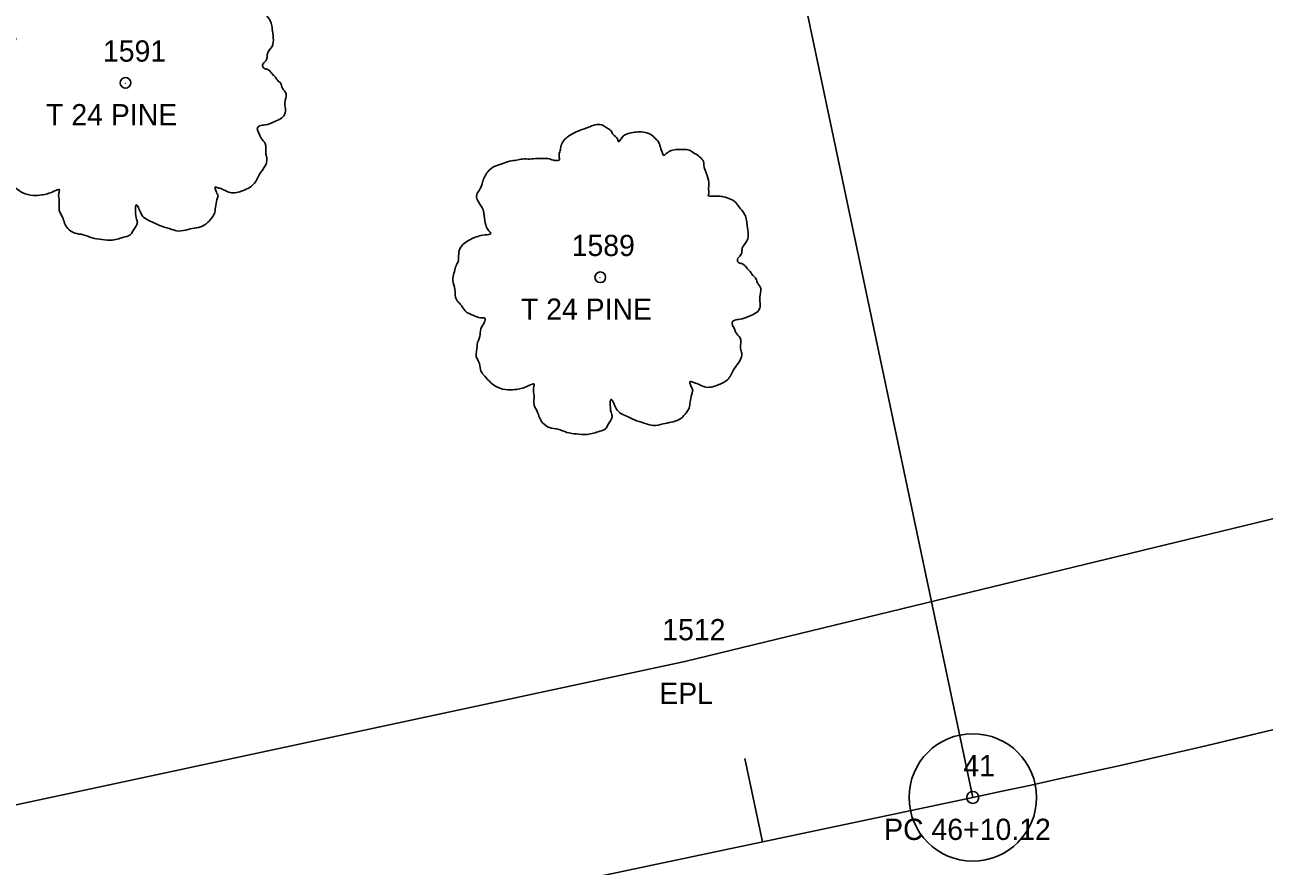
# Model space of a CAD drawing. Extents: x 1964982 to 1970452, y 1116335 to 1119906.
# Drawn here: x 1966640.3 to 1966698.6, y 1117418.7 to 1117458.3 of the extents above; entities that cross this region are included whole.
import ezdxf

# ---------------------------------------------------------------- set-up
doc = ezdxf.new("R2010")
doc.units = 0
for name, color, linetype in [('RD_EX_DV_Prop', 7, 'Continuous'), ('RD_EX_Road', 7, 'Continuous'), ('RD_EX_Road_txCode', 7, 'Continuous'), ('RD_EX_RW', 7, 'Continuous'), ('RD_EX_VEG', 7, 'Continuous'), ('RD_EX_VEG_txCode', 7, 'Continuous'), ('RD_HC_CL', 7, 'Continuous'), ('RD_HC_Data', 7, 'Continuous'), ('RD_HC_Data_Tic', 7, 'Continuous'), ('RD_HC_txCode', 7, 'Continuous'), ('RD_SMD_Locator', 7, 'Continuous')]:
    doc.layers.add(name, color=color, linetype=linetype)

msp = doc.modelspace()

# ---------------------------------------------------------------- linework, layer by layer
at = {"layer": 'RD_EX_DV_Prop'}
msp.add_line((1966425.261, 1117367.215), (1966684.872, 1117421.945), dxfattribs=at)
msp.add_arc((1966579.594, 1117921.318), 510.35, 281.90473, 291.99584, dxfattribs=at)
at = {"layer": 'RD_EX_Road'}
msp.add_lwpolyline([(1966484.547, 1117389.131), (1966531.199, 1117398.733), (1966578.388, 1117408.593), (1966604.527, 1117414.058), (1966624.537, 1117418.323), (1966671.319, 1117428.348), (1966716.506, 1117439.32), (1966736.604, 1117445.59), (1966754.133, 1117451.442), (1966759.658, 1117453.517), (1966769.512, 1117457.475)], dxfattribs=at)
at = {"layer": 'RD_EX_RW'}
msp.add_lwpolyline([(1966484.547, 1117389.131), (1966531.199, 1117398.733), (1966578.388, 1117408.593), (1966604.527, 1117414.058), (1966624.537, 1117418.323), (1966671.319, 1117428.348), (1966716.506, 1117439.32), (1966736.604, 1117445.59), (1966754.133, 1117451.442), (1966759.658, 1117453.517), (1966769.512, 1117457.475)], dxfattribs=at)
at = {"layer": 'RD_EX_VEG'}
for centre, radius in [((1966644.994, 1117455.597), 0.25), ((1966644.994, 1117455.597), 0.25), ((1966644.981, 1117455.578), 0.0001), ((1966644.981, 1117455.578), 0.0001), ((1966667.339, 1117446.441), 0.25), ((1966667.339, 1117446.441), 0.25), ((1966667.326, 1117446.422), 0.0001), ((1966667.326, 1117446.422), 0.0001)]:
    msp.add_circle(centre, radius, dxfattribs=at)
for points in [[(1966645.126, 1117462.764), (1966644.826, 1117462.789), (1966644.501, 1117462.689), (1966644.251, 1117462.589), (1966644.026, 1117462.514), (1966643.801, 1117462.414), (1966643.501, 1117462.24), (1966643.276, 1117462.04), (1966643.151, 1117461.79), (1966643.101, 1117461.565), (1966643.052, 1117461.29), (1966643.052, 1117461.115), (1966642.927, 1117461.09), (1966642.777, 1117461.115), (1966642.527, 1117461.19), (1966642.277, 1117461.19), (1966642.027, 1117461.19), (1966641.677, 1117461.165), (1966641.327, 1117461.165), (1966641.052, 1117461.115), (1966640.728, 1117461.065), (1966640.353, 1117460.94), (1966640.003, 1117460.815), (1966639.703, 1117460.565), (1966639.453, 1117460.09), (1966639.328, 1117459.741), (1966639.178, 1117459.491), (1966639.328, 1117459.041), (1966639.503, 1117458.691), (1966639.528, 1117458.491), (1966639.603, 1117458.066), (1966639.703, 1117457.841), (1966639.828, 1117457.641), (1966639.753, 1117457.617), (1966639.378, 1117457.567), (1966639.078, 1117457.467), (1966638.653, 1117457.242), (1966638.429, 1117457.017), (1966638.329, 1117456.692), (1966638.304, 1117456.342), (1966638.204, 1117456.142), (1966638.129, 1117455.867), (1966638.104, 1117455.792), (1966638.054, 1117455.467), (1966638.154, 1117455.018), (1966638.179, 1117454.668), (1966638.304, 1117454.443), (1966638.454, 1117454.268), (1966638.628, 1117454.018), (1966639.028, 1117453.793), (1966639.353, 1117453.693), (1966639.553, 1117453.668), (1966639.378, 1117453.168), (1966639.328, 1117452.819), (1966639.203, 1117452.419), (1966639.203, 1117452.344), (1966639.153, 1117451.869), (1966639.303, 1117451.544), (1966639.378, 1117451.169), (1966639.553, 1117450.944), (1966639.828, 1117450.645), (1966640.153, 1117450.42), (1966640.653, 1117450.295), (1966641.052, 1117450.32), (1966641.627, 1117450.495), (1966641.877, 1117450.57), (1966641.852, 1117450.395), (1966641.877, 1117450.02), (1966641.877, 1117449.595), (1966642.027, 1117449.27), (1966642.127, 1117448.995), (1966642.277, 1117448.745), (1966642.602, 1117448.521), (1966643.002, 1117448.446), (1966643.426, 1117448.296), (1966643.876, 1117448.221), (1966644.376, 1117448.196), (1966644.976, 1117448.346), (1966645.251, 1117448.471), (1966645.351, 1117448.645), (1966645.55, 1117449.02), (1966645.5, 1117449.245), (1966645.525, 1117449.845), (1966645.625, 1117449.67), (1966645.8, 1117449.32), (1966646.3, 1117449.02), (1966646.7, 1117448.845), (1966647.175, 1117448.695), (1966647.475, 1117448.62), (1966647.949, 1117448.695), (1966648.324, 1117448.77), (1966648.699, 1117448.895), (1966648.999, 1117449.17), (1966649.174, 1117449.445), (1966649.224, 1117449.72), (1966649.299, 1117450.095), (1966649.349, 1117450.27)], [(1966645.126, 1117462.764), (1966644.826, 1117462.789), (1966644.501, 1117462.689), (1966644.251, 1117462.589), (1966644.026, 1117462.514), (1966643.801, 1117462.414), (1966643.501, 1117462.24), (1966643.276, 1117462.04), (1966643.151, 1117461.79), (1966643.101, 1117461.565), (1966643.052, 1117461.29), (1966643.052, 1117461.115), (1966642.927, 1117461.09), (1966642.777, 1117461.115), (1966642.527, 1117461.19), (1966642.277, 1117461.19), (1966642.027, 1117461.19), (1966641.677, 1117461.165), (1966641.327, 1117461.165), (1966641.052, 1117461.115), (1966640.728, 1117461.065), (1966640.353, 1117460.94), (1966640.003, 1117460.815), (1966639.703, 1117460.565), (1966639.453, 1117460.09), (1966639.328, 1117459.741), (1966639.178, 1117459.491), (1966639.328, 1117459.041), (1966639.503, 1117458.691), (1966639.528, 1117458.491), (1966639.603, 1117458.066), (1966639.703, 1117457.841), (1966639.828, 1117457.641), (1966639.753, 1117457.617), (1966639.378, 1117457.567), (1966639.078, 1117457.467), (1966638.653, 1117457.242), (1966638.429, 1117457.017), (1966638.329, 1117456.692), (1966638.304, 1117456.342), (1966638.204, 1117456.142), (1966638.129, 1117455.867), (1966638.104, 1117455.792), (1966638.054, 1117455.467), (1966638.154, 1117455.018), (1966638.179, 1117454.668), (1966638.304, 1117454.443), (1966638.454, 1117454.268), (1966638.628, 1117454.018), (1966639.028, 1117453.793), (1966639.353, 1117453.693), (1966639.553, 1117453.668), (1966639.378, 1117453.168), (1966639.328, 1117452.819), (1966639.203, 1117452.419), (1966639.203, 1117452.344), (1966639.153, 1117451.869), (1966639.303, 1117451.544), (1966639.378, 1117451.169), (1966639.553, 1117450.944), (1966639.828, 1117450.645), (1966640.153, 1117450.42), (1966640.653, 1117450.295), (1966641.052, 1117450.32), (1966641.627, 1117450.495), (1966641.877, 1117450.57), (1966641.852, 1117450.395), (1966641.877, 1117450.02), (1966641.877, 1117449.595), (1966642.027, 1117449.27), (1966642.127, 1117448.995), (1966642.277, 1117448.745), (1966642.602, 1117448.521), (1966643.002, 1117448.446), (1966643.426, 1117448.296), (1966643.876, 1117448.221), (1966644.376, 1117448.196), (1966644.976, 1117448.346), (1966645.251, 1117448.471), (1966645.351, 1117448.645), (1966645.55, 1117449.02), (1966645.5, 1117449.245), (1966645.525, 1117449.845), (1966645.625, 1117449.67), (1966645.8, 1117449.32), (1966646.3, 1117449.02), (1966646.7, 1117448.845), (1966647.175, 1117448.695), (1966647.475, 1117448.62), (1966647.949, 1117448.695), (1966648.324, 1117448.77), (1966648.699, 1117448.895), (1966648.999, 1117449.17), (1966649.174, 1117449.445), (1966649.224, 1117449.72), (1966649.299, 1117450.095), (1966649.349, 1117450.27)], [(1966649.349, 1117450.27), (1966649.274, 1117450.445), (1966649.224, 1117450.695), (1966649.299, 1117450.67), (1966649.474, 1117450.62), (1966649.749, 1117450.495), (1966649.974, 1117450.42), (1966650.298, 1117450.445), (1966650.573, 1117450.545), (1966651.023, 1117450.82), (1966651.298, 1117451.294), (1966651.573, 1117451.694), (1966651.648, 1117452.019), (1966651.598, 1117452.244), (1966651.573, 1117452.744), (1966651.373, 1117452.994), (1966651.323, 1117453.118), (1966651.223, 1117453.518), (1966651.298, 1117453.568), (1966651.573, 1117453.618), (1966651.948, 1117453.743), (1966652.223, 1117453.868), (1966652.447, 1117454.043), (1966652.522, 1117454.268), (1966652.497, 1117454.668), (1966652.547, 1117455.068), (1966652.472, 1117455.218), (1966652.372, 1117455.367), (1966652.297, 1117455.567), (1966652.148, 1117455.717), (1966652.048, 1117455.867), (1966651.948, 1117455.967), (1966651.823, 1117456.117), (1966651.648, 1117456.242), (1966651.498, 1117456.292), (1966651.448, 1117456.442), (1966651.598, 1117456.642), (1966651.648, 1117456.742), (1966651.673, 1117456.967), (1966651.898, 1117457.317), (1966651.948, 1117457.716), (1966651.898, 1117458.141), (1966651.848, 1117458.416), (1966651.698, 1117458.691), (1966651.498, 1117458.941), (1966651.373, 1117459.116), (1966651.198, 1117459.241), (1966650.873, 1117459.366), (1966650.623, 1117459.416), (1966650.273, 1117459.416), (1966650.073, 1117459.466), (1966650.098, 1117459.516), (1966650.098, 1117459.666), (1966650.098, 1117459.941), (1966650.023, 1117460.39), (1966649.874, 1117460.89), (1966649.874, 1117460.915), (1966649.774, 1117461.165), (1966649.549, 1117461.365), (1966649.374, 1117461.465), (1966649.174, 1117461.59), (1966648.924, 1117461.615), (1966648.624, 1117461.615), (1966648.349, 1117461.565), (1966648.149, 1117461.465), (1966647.974, 1117461.34), (1966647.899, 1117461.49), (1966647.799, 1117461.79), (1966647.749, 1117461.94), (1966647.6, 1117462.115), (1966647.375, 1117462.314), (1966646.925, 1117462.439), (1966646.3, 1117462.364), (1966646, 1117462.165), (1966645.85, 1117461.99), (1966645.8, 1117462.115), (1966645.6, 1117462.314), (1966645.5, 1117462.489), (1966645.326, 1117462.614), (1966645.176, 1117462.714), (1966645.076, 1117462.764)], [(1966649.349, 1117450.27), (1966649.274, 1117450.445), (1966649.224, 1117450.695), (1966649.299, 1117450.67), (1966649.474, 1117450.62), (1966649.749, 1117450.495), (1966649.974, 1117450.42), (1966650.298, 1117450.445), (1966650.573, 1117450.545), (1966651.023, 1117450.82), (1966651.298, 1117451.294), (1966651.573, 1117451.694), (1966651.648, 1117452.019), (1966651.598, 1117452.244), (1966651.573, 1117452.744), (1966651.373, 1117452.994), (1966651.323, 1117453.118), (1966651.223, 1117453.518), (1966651.298, 1117453.568), (1966651.573, 1117453.618), (1966651.948, 1117453.743), (1966652.223, 1117453.868), (1966652.447, 1117454.043), (1966652.522, 1117454.268), (1966652.497, 1117454.668), (1966652.547, 1117455.068), (1966652.472, 1117455.218), (1966652.372, 1117455.367), (1966652.297, 1117455.567), (1966652.148, 1117455.717), (1966652.048, 1117455.867), (1966651.948, 1117455.967), (1966651.823, 1117456.117), (1966651.648, 1117456.242), (1966651.498, 1117456.292), (1966651.448, 1117456.442), (1966651.598, 1117456.642), (1966651.648, 1117456.742), (1966651.673, 1117456.967), (1966651.898, 1117457.317), (1966651.948, 1117457.716), (1966651.898, 1117458.141), (1966651.848, 1117458.416), (1966651.698, 1117458.691), (1966651.498, 1117458.941), (1966651.373, 1117459.116), (1966651.198, 1117459.241), (1966650.873, 1117459.366), (1966650.623, 1117459.416), (1966650.273, 1117459.416), (1966650.073, 1117459.466), (1966650.098, 1117459.516), (1966650.098, 1117459.666), (1966650.098, 1117459.941), (1966650.023, 1117460.39), (1966649.874, 1117460.89), (1966649.874, 1117460.915), (1966649.774, 1117461.165), (1966649.549, 1117461.365), (1966649.374, 1117461.465), (1966649.174, 1117461.59), (1966648.924, 1117461.615), (1966648.624, 1117461.615), (1966648.349, 1117461.565), (1966648.149, 1117461.465), (1966647.974, 1117461.34), (1966647.899, 1117461.49), (1966647.799, 1117461.79), (1966647.749, 1117461.94), (1966647.6, 1117462.115), (1966647.375, 1117462.314), (1966646.925, 1117462.439), (1966646.3, 1117462.364), (1966646, 1117462.165), (1966645.85, 1117461.99), (1966645.8, 1117462.115), (1966645.6, 1117462.314), (1966645.5, 1117462.489), (1966645.326, 1117462.614), (1966645.176, 1117462.714), (1966645.076, 1117462.764)], [(1966667.471, 1117453.608), (1966667.171, 1117453.633), (1966666.846, 1117453.533), (1966666.596, 1117453.433), (1966666.371, 1117453.358), (1966666.146, 1117453.258), (1966665.846, 1117453.083), (1966665.622, 1117452.883), (1966665.497, 1117452.634), (1966665.447, 1117452.409), (1966665.397, 1117452.134), (1966665.397, 1117451.959), (1966665.272, 1117451.934), (1966665.122, 1117451.959), (1966664.872, 1117452.034), (1966664.622, 1117452.034), (1966664.372, 1117452.034), (1966664.022, 1117452.009), (1966663.672, 1117452.009), (1966663.398, 1117451.959), (1966663.073, 1117451.909), (1966662.698, 1117451.784), (1966662.348, 1117451.659), (1966662.048, 1117451.409), (1966661.798, 1117450.934), (1966661.673, 1117450.584), (1966661.523, 1117450.335), (1966661.673, 1117449.885), (1966661.848, 1117449.535), (1966661.873, 1117449.335), (1966661.948, 1117448.91), (1966662.048, 1117448.685), (1966662.173, 1117448.485), (1966662.098, 1117448.46), (1966661.723, 1117448.41), (1966661.423, 1117448.31), (1966660.999, 1117448.086), (1966660.774, 1117447.861), (1966660.674, 1117447.536), (1966660.649, 1117447.186), (1966660.549, 1117446.986), (1966660.474, 1117446.711), (1966660.449, 1117446.636), (1966660.399, 1117446.311), (1966660.499, 1117445.861), (1966660.524, 1117445.512), (1966660.649, 1117445.287), (1966660.799, 1117445.112), (1966660.974, 1117444.862), (1966661.373, 1117444.637), (1966661.698, 1117444.537), (1966661.898, 1117444.512), (1966661.723, 1117444.012), (1966661.673, 1117443.662), (1966661.548, 1117443.263), (1966661.548, 1117443.188), (1966661.498, 1117442.713), (1966661.648, 1117442.388), (1966661.723, 1117442.013), (1966661.898, 1117441.788), (1966662.173, 1117441.488), (1966662.498, 1117441.264), (1966662.998, 1117441.139), (1966663.398, 1117441.164), (1966663.972, 1117441.338), (1966664.222, 1117441.413), (1966664.197, 1117441.239), (1966664.222, 1117440.864), (1966664.222, 1117440.439), (1966664.372, 1117440.114), (1966664.472, 1117439.839), (1966664.622, 1117439.589), (1966664.947, 1117439.364), (1966665.347, 1117439.289), (1966665.771, 1117439.139), (1966666.221, 1117439.064), (1966666.721, 1117439.039), (1966667.321, 1117439.189), (1966667.596, 1117439.314), (1966667.696, 1117439.489), (1966667.896, 1117439.864), (1966667.846, 1117440.089), (1966667.871, 1117440.689), (1966667.97, 1117440.514), (1966668.145, 1117440.164), (1966668.645, 1117439.864), (1966669.045, 1117439.689), (1966669.52, 1117439.539), (1966669.82, 1117439.464), (1966670.294, 1117439.539), (1966670.669, 1117439.614), (1966671.044, 1117439.739), (1966671.344, 1117440.014), (1966671.519, 1117440.289), (1966671.569, 1117440.564), (1966671.644, 1117440.939), (1966671.694, 1117441.114)], [(1966667.471, 1117453.608), (1966667.171, 1117453.633), (1966666.846, 1117453.533), (1966666.596, 1117453.433), (1966666.371, 1117453.358), (1966666.146, 1117453.258), (1966665.846, 1117453.083), (1966665.622, 1117452.883), (1966665.497, 1117452.634), (1966665.447, 1117452.409), (1966665.397, 1117452.134), (1966665.397, 1117451.959), (1966665.272, 1117451.934), (1966665.122, 1117451.959), (1966664.872, 1117452.034), (1966664.622, 1117452.034), (1966664.372, 1117452.034), (1966664.022, 1117452.009), (1966663.672, 1117452.009), (1966663.398, 1117451.959), (1966663.073, 1117451.909), (1966662.698, 1117451.784), (1966662.348, 1117451.659), (1966662.048, 1117451.409), (1966661.798, 1117450.934), (1966661.673, 1117450.584), (1966661.523, 1117450.335), (1966661.673, 1117449.885), (1966661.848, 1117449.535), (1966661.873, 1117449.335), (1966661.948, 1117448.91), (1966662.048, 1117448.685), (1966662.173, 1117448.485), (1966662.098, 1117448.46), (1966661.723, 1117448.41), (1966661.423, 1117448.31), (1966660.999, 1117448.086), (1966660.774, 1117447.861), (1966660.674, 1117447.536), (1966660.649, 1117447.186), (1966660.549, 1117446.986), (1966660.474, 1117446.711), (1966660.449, 1117446.636), (1966660.399, 1117446.311), (1966660.499, 1117445.861), (1966660.524, 1117445.512), (1966660.649, 1117445.287), (1966660.799, 1117445.112), (1966660.974, 1117444.862), (1966661.373, 1117444.637), (1966661.698, 1117444.537), (1966661.898, 1117444.512), (1966661.723, 1117444.012), (1966661.673, 1117443.662), (1966661.548, 1117443.263), (1966661.548, 1117443.188), (1966661.498, 1117442.713), (1966661.648, 1117442.388), (1966661.723, 1117442.013), (1966661.898, 1117441.788), (1966662.173, 1117441.488), (1966662.498, 1117441.264), (1966662.998, 1117441.139), (1966663.398, 1117441.164), (1966663.972, 1117441.338), (1966664.222, 1117441.413), (1966664.197, 1117441.239), (1966664.222, 1117440.864), (1966664.222, 1117440.439), (1966664.372, 1117440.114), (1966664.472, 1117439.839), (1966664.622, 1117439.589), (1966664.947, 1117439.364), (1966665.347, 1117439.289), (1966665.771, 1117439.139), (1966666.221, 1117439.064), (1966666.721, 1117439.039), (1966667.321, 1117439.189), (1966667.596, 1117439.314), (1966667.696, 1117439.489), (1966667.896, 1117439.864), (1966667.846, 1117440.089), (1966667.871, 1117440.689), (1966667.97, 1117440.514), (1966668.145, 1117440.164), (1966668.645, 1117439.864), (1966669.045, 1117439.689), (1966669.52, 1117439.539), (1966669.82, 1117439.464), (1966670.294, 1117439.539), (1966670.669, 1117439.614), (1966671.044, 1117439.739), (1966671.344, 1117440.014), (1966671.519, 1117440.289), (1966671.569, 1117440.564), (1966671.644, 1117440.939), (1966671.694, 1117441.114)], [(1966671.694, 1117441.114), (1966671.619, 1117441.289), (1966671.569, 1117441.538), (1966671.644, 1117441.513), (1966671.819, 1117441.463), (1966672.094, 1117441.338), (1966672.319, 1117441.264), (1966672.643, 1117441.289), (1966672.918, 1117441.388), (1966673.368, 1117441.663), (1966673.643, 1117442.138), (1966673.918, 1117442.538), (1966673.993, 1117442.863), (1966673.943, 1117443.088), (1966673.918, 1117443.587), (1966673.718, 1117443.837), (1966673.668, 1117443.962), (1966673.568, 1117444.362), (1966673.643, 1117444.412), (1966673.918, 1117444.462), (1966674.293, 1117444.587), (1966674.568, 1117444.712), (1966674.793, 1117444.887), (1966674.867, 1117445.112), (1966674.843, 1117445.512), (1966674.892, 1117445.911), (1966674.818, 1117446.061), (1966674.718, 1117446.211), (1966674.643, 1117446.411), (1966674.493, 1117446.561), (1966674.393, 1117446.711), (1966674.293, 1117446.811), (1966674.168, 1117446.961), (1966673.993, 1117447.086), (1966673.843, 1117447.136), (1966673.793, 1117447.286), (1966673.943, 1117447.486), (1966673.993, 1117447.586), (1966674.018, 1117447.811), (1966674.243, 1117448.16), (1966674.293, 1117448.56), (1966674.243, 1117448.985), (1966674.193, 1117449.26), (1966674.043, 1117449.535), (1966673.843, 1117449.785), (1966673.718, 1117449.96), (1966673.543, 1117450.085), (1966673.218, 1117450.21), (1966672.968, 1117450.26), (1966672.618, 1117450.26), (1966672.419, 1117450.31), (1966672.444, 1117450.36), (1966672.444, 1117450.509), (1966672.444, 1117450.784), (1966672.369, 1117451.234), (1966672.219, 1117451.734), (1966672.219, 1117451.759), (1966672.119, 1117452.009), (1966671.894, 1117452.209), (1966671.719, 1117452.309), (1966671.519, 1117452.434), (1966671.269, 1117452.459), (1966670.969, 1117452.459), (1966670.694, 1117452.409), (1966670.494, 1117452.309), (1966670.319, 1117452.184), (1966670.244, 1117452.334), (1966670.145, 1117452.634), (1966670.095, 1117452.783), (1966669.945, 1117452.958), (1966669.72, 1117453.158), (1966669.27, 1117453.283), (1966668.645, 1117453.208), (1966668.345, 1117453.008), (1966668.195, 1117452.833), (1966668.145, 1117452.958), (1966667.945, 1117453.158), (1966667.846, 1117453.333), (1966667.671, 1117453.458), (1966667.521, 1117453.558), (1966667.421, 1117453.608)], [(1966671.694, 1117441.114), (1966671.619, 1117441.289), (1966671.569, 1117441.538), (1966671.644, 1117441.513), (1966671.819, 1117441.463), (1966672.094, 1117441.338), (1966672.319, 1117441.264), (1966672.643, 1117441.289), (1966672.918, 1117441.388), (1966673.368, 1117441.663), (1966673.643, 1117442.138), (1966673.918, 1117442.538), (1966673.993, 1117442.863), (1966673.943, 1117443.088), (1966673.918, 1117443.587), (1966673.718, 1117443.837), (1966673.668, 1117443.962), (1966673.568, 1117444.362), (1966673.643, 1117444.412), (1966673.918, 1117444.462), (1966674.293, 1117444.587), (1966674.568, 1117444.712), (1966674.793, 1117444.887), (1966674.867, 1117445.112), (1966674.843, 1117445.512), (1966674.892, 1117445.911), (1966674.818, 1117446.061), (1966674.718, 1117446.211), (1966674.643, 1117446.411), (1966674.493, 1117446.561), (1966674.393, 1117446.711), (1966674.293, 1117446.811), (1966674.168, 1117446.961), (1966673.993, 1117447.086), (1966673.843, 1117447.136), (1966673.793, 1117447.286), (1966673.943, 1117447.486), (1966673.993, 1117447.586), (1966674.018, 1117447.811), (1966674.243, 1117448.16), (1966674.293, 1117448.56), (1966674.243, 1117448.985), (1966674.193, 1117449.26), (1966674.043, 1117449.535), (1966673.843, 1117449.785), (1966673.718, 1117449.96), (1966673.543, 1117450.085), (1966673.218, 1117450.21), (1966672.968, 1117450.26), (1966672.618, 1117450.26), (1966672.419, 1117450.31), (1966672.444, 1117450.36), (1966672.444, 1117450.509), (1966672.444, 1117450.784), (1966672.369, 1117451.234), (1966672.219, 1117451.734), (1966672.219, 1117451.759), (1966672.119, 1117452.009), (1966671.894, 1117452.209), (1966671.719, 1117452.309), (1966671.519, 1117452.434), (1966671.269, 1117452.459), (1966670.969, 1117452.459), (1966670.694, 1117452.409), (1966670.494, 1117452.309), (1966670.319, 1117452.184), (1966670.244, 1117452.334), (1966670.145, 1117452.634), (1966670.095, 1117452.783), (1966669.945, 1117452.958), (1966669.72, 1117453.158), (1966669.27, 1117453.283), (1966668.645, 1117453.208), (1966668.345, 1117453.008), (1966668.195, 1117452.833), (1966668.145, 1117452.958), (1966667.945, 1117453.158), (1966667.846, 1117453.333), (1966667.671, 1117453.458), (1966667.521, 1117453.558), (1966667.421, 1117453.608)]]:
    msp.add_spline(points, degree=3, dxfattribs=at)
at = {"layer": 'RD_HC_CL'}
msp.add_line((1966425.261, 1117367.215), (1966684.871, 1117421.945), dxfattribs=at)
msp.add_arc((1966579.594, 1117921.318), 510.35, 281.90472, 291.99584, dxfattribs=at)
at = {"layer": 'RD_HC_Data'}
msp.add_line((1966684.871, 1117421.945), (1966664.447, 1117518.825), dxfattribs=at)
for radius in [3, 0.282]:
    msp.add_circle((1966684.871, 1117421.945), radius, dxfattribs=at)
at = {"layer": 'RD_HC_Data_Tic'}
msp.add_line((1966674.973, 1117419.859), (1966674.148, 1117423.773), dxfattribs=at)
at = {"layer": 'RD_SMD_Locator'}
for centre in [(1966671.319, 1117428.348), (1966671.319, 1117428.348), (1966684.871, 1117421.945), (1966684.871, 1117421.945)]:
    msp.add_circle(centre, 0.001, dxfattribs=at)

# ---------------------------------------------------------------- texts
at = {"layer": 'RD_EX_Road_txCode'}
for s, p in [('1512', (1966670.256, 1117429.348)), ('1512', (1966670.256, 1117429.348)), ('EPL', (1966670.114, 1117426.348)), ('EPL', (1966670.114, 1117426.348))]:
    msp.add_text(s, height=1, dxfattribs=at).set_placement(p)
at = {"layer": 'RD_EX_VEG_txCode'}
for s, p in [('1591', (1966643.931, 1117456.597)), ('1591', (1966643.931, 1117456.597)), ('T 24 PINE', (1966641.257, 1117453.597)), ('T 24 PINE', (1966641.257, 1117453.597)), ('1589', (1966665.992, 1117447.441)), ('1589', (1966665.992, 1117447.441)), ('T 24 PINE', (1966663.603, 1117444.441)), ('T 24 PINE', (1966663.603, 1117444.441))]:
    msp.add_text(s, height=1, dxfattribs=at).set_placement(p)
at = {"layer": 'RD_HC_txCode'}
for s, p in [('41', (1966684.423, 1117422.945)), ('41', (1966684.423, 1117422.945)), ('PC 46+10.12', (1966680.698, 1117419.945)), ('PC 46+10.12', (1966680.698, 1117419.945))]:
    msp.add_text(s, height=1, dxfattribs=at).set_placement(p)

doc.saveas('drawing.dxf')
